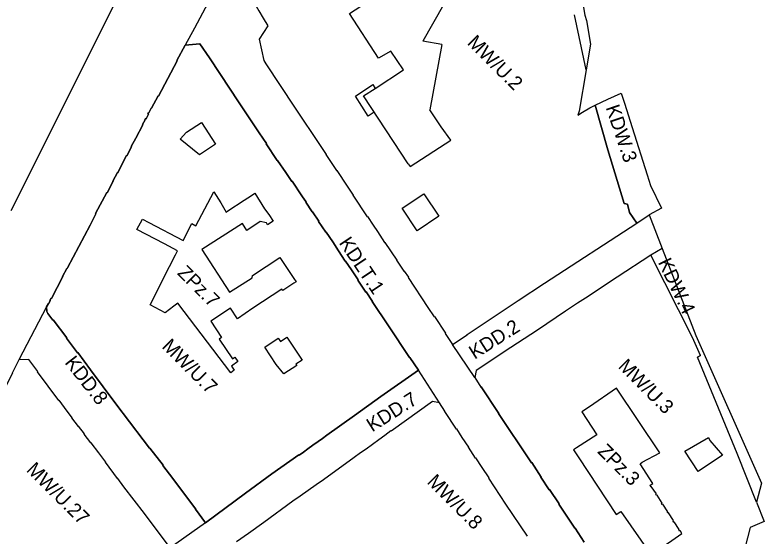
# Model space of a CAD drawing. Extents: x 7423835 to 7425280, y 5546086 to 5547600.
# Drawn here: x 7424423.3 to 7424744.2, y 5546978.5 to 5547201.6 of the extents above; entities that cross this region are included whole.
import ezdxf

# ---------------------------------------------------------------- set-up
doc = ezdxf.new("R2010")
doc.units = 0
for name, color, linetype in [('linie rozgraniczające', 7, 'Continuous'), ('nieprzekraczalne linie zabudowy', 7, 'Continuous'), ('obowiazujace linie zabudowy', 7, 'Continuous'), ('przeznaczenia terenów', 7, 'Continuous')]:
    doc.layers.add(name, color=color, linetype=linetype)

msp = doc.modelspace()

# ---------------------------------------------------------------- linework, layer by layer
at = {"layer": 'linie rozgraniczające'}
for p, q in [((7424421.63, 5547117.9), (7424483.52, 5547241.43)), ((7424668.04, 5547178.09), (7424663, 5547201.56)), ((7424606.16, 5547188.94), (7424598.05, 5547190.36)), ((7424606.16, 5547188.94), (7424601.01, 5547160.97)), ((7424689.69, 5547112.43), (7424694.91, 5547115.93)), ((7424436.81, 5547076.59), (7424424.95, 5547053.95)), ((7424620.22, 5547046.37), (7424610.78, 5547060.48)), ((7424716.92, 5547055.72), (7424715.66, 5547055.1)), ((7424605.11, 5547035.55), (7424596.09, 5547049.53)), ((7424699.58, 5547014.05), (7424681, 5547041.75)), ((7424666.11, 5547031.66), (7424672.53, 5547021.84)), ((7424664.9, 5547011.99), (7424680.83, 5546987.74)), ((7424504.88, 5546984.18), (7424489.79, 5546973.41))]:
    msp.add_line(p, q, dxfattribs=at)
for points in [[(7424515.02, 5547224.22), (7424514.03, 5547222.22), (7424510.28, 5547215.04), (7424500.2, 5547195.98), (7424496.14, 5547188.61)], [(7424515.06, 5547224.71), (7424515.02, 5547224.22), (7424515.98, 5547223.73), (7424524.29, 5547209.32), (7424526.02, 5547206.37), (7424527.74, 5547203.41), (7424529.66, 5547200.13), (7424531.58, 5547196.85), (7424531.58, 5547196.85), (7424527.83, 5547191.15), (7424529.92, 5547182.06), (7424530.79, 5547180.62)], [(7424589.68, 5547178.04), (7424589.68, 5547178.04), (7424584.25, 5547186.11), (7424578.98, 5547183.11), (7424566.55, 5547202.13), (7424571.43, 5547205.35), (7424569.51, 5547209.13), (7424567.47, 5547215.13), (7424566.64, 5547215.54), (7424566.64, 5547215.54)], [(7424665.83, 5547210.62), (7424667.48, 5547201.5), (7424668.06, 5547199.15), (7424669.81, 5547189), (7424668.04, 5547178.09), (7424664.92, 5547160.36), (7424664.39, 5547158.6), (7424666.46, 5547159.91), (7424669.51, 5547161.84), (7424671.82, 5547162.96), (7424677.22, 5547165.58), (7424682.93, 5547168.09), (7424684.38, 5547163.8), (7424687.66, 5547153.42), (7424694.13, 5547133.14), (7424695.52, 5547128.62), (7424700.33, 5547118.84), (7424694.91, 5547115.93), (7424700.59, 5547101.52), (7424714.9, 5547064.29), (7424743.15, 5547001.11), (7424741.02, 5546992.9), (7424744.18, 5546984.74), (7424738.23, 5546982.17), (7424733.48, 5546963.9)], [(7424606.91, 5547205.94), (7424598.05, 5547190.36)], [(7424436.81, 5547076.59), (7424437.63, 5547078.09), (7424437.76, 5547078.01), (7424438.36, 5547079.29), (7424438.28, 5547079.34), (7424438.77, 5547080.27), (7424438.91, 5547080.19), (7424443.83, 5547089.57), (7424443.69, 5547089.64), (7424445.49, 5547093.08), (7424445.67, 5547093.01), (7424445.78, 5547093.3), (7424455.43, 5547111.63), (7424457.98, 5547116.45), (7424457.83, 5547116.52), (7424462.59, 5547125.49), (7424462.73, 5547125.41), (7424465.38, 5547130.41), (7424465.27, 5547130.47), (7424467.15, 5547134.06), (7424467.29, 5547133.99), (7424469.27, 5547137.79), (7424469.15, 5547137.85), (7424471.08, 5547141.39), (7424471.21, 5547141.32), (7424473.24, 5547145.14), (7424473.12, 5547145.23), (7424475.04, 5547148.84), (7424478.06, 5547154.51), (7424477.97, 5547154.61), (7424479.04, 5547156.62), (7424478.96, 5547156.69), (7424479.2, 5547157.17), (7424479.44, 5547157.05), (7424480.45, 5547159.14), (7424480.27, 5547159.22), (7424480.5, 5547159.7), (7424480.62, 5547159.64), (7424481.7, 5547161.67), (7424481.82, 5547161.6), (7424484.63, 5547166.89), (7424484.75, 5547166.83), (7424492.83, 5547181.99), (7424492.67, 5547182.08), (7424496.14, 5547188.61)], [(7424496.14, 5547188.61), (7424502.52, 5547189.17), (7424506.61, 5547183.15), (7424515.48, 5547169.78), (7424518.8, 5547164.78), (7424527.86, 5547151.11), (7424530.97, 5547146.47), (7424530.85, 5547146.39), (7424535.56, 5547139.21), (7424535.71, 5547139.32), (7424539.35, 5547134.14), (7424541.91, 5547130.25), (7424542.04, 5547130.34), (7424546.22, 5547124.15), (7424547.44, 5547122.32), (7424547.98, 5547121.53), (7424547.85, 5547121.44), (7424550.62, 5547117.25), (7424550.76, 5547117.34), (7424553.53, 5547113.23), (7424553.36, 5547113.12), (7424556.44, 5547108.6), (7424556.61, 5547108.63), (7424559.39, 5547104.47), (7424561.94, 5547100.62), (7424561.84, 5547100.52), (7424564.78, 5547096.13), (7424564.91, 5547096.19), (7424567.47, 5547092.38), (7424570.27, 5547088.19), (7424570.15, 5547088.08), (7424573.59, 5547082.95), (7424573.73, 5547083.02), (7424576.44, 5547078.94), (7424576.32, 5547078.85), (7424583.29, 5547068.52), (7424592.35, 5547054.87), (7424592.48, 5547054.93), (7424596.09, 5547049.53)], [(7424530.79, 5547180.62), (7424543.07, 5547162.12), (7424554.29, 5547145.24), (7424556.56, 5547141.85), (7424556.44, 5547141.76), (7424561, 5547134.94), (7424561.13, 5547135.03), (7424565.62, 5547128.32), (7424568.22, 5547124.44), (7424568.09, 5547124.35), (7424574.23, 5547115.19), (7424574.37, 5547115.26), (7424576.8, 5547111.61), (7424578.66, 5547108.86), (7424578.54, 5547108.79), (7424581.65, 5547104.08), (7424581.78, 5547104.16), (7424586.86, 5547096.63), (7424586.73, 5547096.55), (7424589.87, 5547091.87), (7424590.01, 5547091.94), (7424591.82, 5547089.24), (7424591.68, 5547089.15), (7424600.21, 5547076.35), (7424602.91, 5547072.33), (7424603.05, 5547072.41), (7424607.77, 5547065.33), (7424607.63, 5547065.24), (7424610.78, 5547060.48), (7424617.04, 5547064.63), (7424616.97, 5547064.75), (7424630.76, 5547073.82), (7424638.92, 5547079.25), (7424650.2, 5547086.74), (7424689.69, 5547112.43)], [(7424572.65, 5547166.9), (7424577.62, 5547170.15), (7424589.68, 5547178.05)], [(7424591.75, 5547137.85), (7424585.49, 5547147.37), (7424572.65, 5547166.9)], [(7424671.82, 5547162.96), (7424677.23, 5547143.81), (7424684.32, 5547120.8), (7424685.76, 5547120.53), (7424686.5, 5547117.04), (7424689.69, 5547112.43)], [(7424609.97, 5547147.98), (7424605.83, 5547153.73), (7424601.01, 5547160.97)], [(7424591.75, 5547137.85), (7424592.62, 5547136.65), (7424609.97, 5547147.98)], [(7424700.59, 5547101.52), (7424695.7, 5547098.75), (7424681.3, 5547089.27), (7424667.63, 5547080.28), (7424664.28, 5547078.12), (7424659.15, 5547074.74), (7424647.12, 5547066.65), (7424635.68, 5547059.25), (7424620.81, 5547049.34), (7424620.22, 5547046.37), (7424622.92, 5547042.19), (7424623.04, 5547042.28)], [(7424713.55, 5547063.4), (7424695.7, 5547098.75)], [(7424596.09, 5547049.53), (7424580.08, 5547038.16), (7424568.7, 5547030.05), (7424556.86, 5547021.6), (7424554.99, 5547020.25), (7424553.11, 5547018.9), (7424550.92, 5547017.33), (7424548.74, 5547015.76), (7424546.88, 5547014.42), (7424545.02, 5547013.09), (7424544.93, 5547013.21), (7424533.35, 5547005.05), (7424522.08, 5546996.86), (7424504.88, 5546984.18), (7424500.58, 5546989.94), (7424500.71, 5546990.04), (7424489.46, 5547004.95), (7424486.61, 5547008.64), (7424486.73, 5547008.75), (7424481.1, 5547016.14), (7424480.94, 5547016.09), (7424478.24, 5547019.6), (7424466.56, 5547035.13), (7424455.59, 5547049.63), (7424450.15, 5547056.99), (7424450.01, 5547056.88), (7424447.89, 5547059.79), (7424445.32, 5547063.2), (7424445.44, 5547063.29), (7424439.66, 5547070.99), (7424439.52, 5547070.89), (7424437.34, 5547073.69), (7424436.95, 5547074.62), (7424436.81, 5547076.59)], [(7424716.92, 5547055.72), (7424713.55, 5547063.4)], [(7424429.17, 5547053.99), (7424424.95, 5547053.95), (7424422.08, 5547048.27), (7424422.23, 5547048.2), (7424414.59, 5547033.43), (7424414.46, 5547033.49), (7424412.33, 5547029.27), (7424412.45, 5547029.21), (7424410.31, 5547025.17), (7424408.29, 5547021.34), (7424408.44, 5547021.27), (7424403.06, 5547010.72), (7424402.91, 5547010.8), (7424401.09, 5547007.28), (7424398.43, 5547002.08), (7424398.57, 5547002.01), (7424396.07, 5546997.23), (7424395.93, 5546997.28), (7424393.21, 5546992.04), (7424393.33, 5546991.97), (7424388.52, 5546982.69), (7424388.38, 5546982.76), (7424386.34, 5546978.7)], [(7424489.79, 5546973.41), (7424478.72, 5546988.05), (7424469.96, 5546999.56), (7424467.35, 5547003.14), (7424467.22, 5547003.04), (7424462.05, 5547010.07), (7424462.18, 5547010.16), (7424459.24, 5547014.08), (7424455.89, 5547018.43), (7424455.78, 5547018.34), (7424452.96, 5547022.09), (7424453.08, 5547022.18), (7424450.55, 5547025.5), (7424450.44, 5547025.42), (7424447.65, 5547029.07), (7424447.74, 5547029.14), (7424444.52, 5547033.47), (7424442.2, 5547036.58), (7424442.08, 5547036.5), (7424432.98, 5547048.78), (7424433.1, 5547048.87), (7424429.17, 5547053.99)], [(7424741.02, 5546992.9), (7424732.67, 5547013.81), (7424715.66, 5547055.1)], [(7424667.19, 5546975.89), (7424663.24, 5546981.87), (7424663.1, 5546981.79), (7424659.66, 5546986.99), (7424656.23, 5546992.16), (7424656.38, 5546992.25), (7424652.29, 5546998.39), (7424652.15, 5546998.3), (7424648.62, 5547003.67), (7424648.73, 5547003.74), (7424644.7, 5547009.88), (7424644.55, 5547009.79), (7424641.07, 5547014.97), (7424633.29, 5547026.68), (7424630.46, 5547030.9), (7424630.6, 5547030.99), (7424623.04, 5547042.28)], [(7424681, 5547041.75), (7424669.36, 5547033.81), (7424666.11, 5547031.66)], [(7424642.84, 5546978.38), (7424633.62, 5546992.17), (7424626.24, 5547003.28), (7424626.37, 5547003.36), (7424623.41, 5547007.85), (7424620.74, 5547011.88), (7424620.6, 5547011.79), (7424617.52, 5547016.45), (7424617.65, 5547016.55), (7424614.92, 5547020.7), (7424612.51, 5547024.34), (7424612.4, 5547024.26), (7424607.4, 5547031.84), (7424607.51, 5547031.91), (7424605.11, 5547035.55), (7424602.15, 5547036.09), (7424584.43, 5547023.32), (7424584.34, 5547023.44), (7424581.73, 5547021.55), (7424579.21, 5547019.67), (7424576.4, 5547017.65), (7424573.7, 5547015.72), (7424571.38, 5547014.04), (7424568.62, 5547012.03), (7424555.43, 5547002.5), (7424552.28, 5547000.32), (7424545.43, 5546995.48), (7424542.33, 5546993.35), (7424529.87, 5546984.21), (7424523.35, 5546979.58), (7424518.2, 5546975.95)], [(7424672.53, 5547021.84), (7424663.88, 5547016.26), (7424662.6, 5547015.44), (7424664.9, 5547011.99)], [(7424709.02, 5546979.52), (7424708.2, 5546980.77), (7424707.94, 5546980.61), (7424707.64, 5546981.08), (7424707.9, 5546981.24), (7424705.72, 5546984.57), (7424705.5, 5546984.42), (7424705.19, 5546984.89), (7424705.41, 5546985.05), (7424703.25, 5546988.33), (7424703.04, 5546988.2), (7424702.79, 5546988.73), (7424702.94, 5546988.84), (7424700.84, 5546992.11), (7424700.61, 5546991.98), (7424700.3, 5546992.46), (7424700.52, 5546992.6), (7424698.36, 5546995.95), (7424698.15, 5546995.81), (7424697.86, 5546996.4), (7424698.1, 5546996.51), (7424695.9, 5546999.73), (7424695.67, 5546999.6), (7424695.36, 5547000.2), (7424696.57, 5547000.98), (7424691.09, 5547009.45), (7424692.04, 5547010.07), (7424699.58, 5547014.05)], [(7424680.83, 5546987.74), (7424682.81, 5546988.93), (7424695.69, 5546970.54)], [(7424695.69, 5546970.54), (7424703.23, 5546975.57), (7424709.02, 5546979.52)]]:
    msp.add_lwpolyline(points, dxfattribs=at)
msp.add_lwpolyline([(7424536.79, 5547097.73), (7424542.79, 5547088.68), (7424543.7, 5547087.31), (7424543.69, 5547087.3), (7424542.78, 5547086.75), (7424537.97, 5547083.66), (7424537.61, 5547084.22), (7424525.25, 5547075.96), (7424525.25, 5547075.96), (7424525.25, 5547075.96), (7424525.25, 5547075.96), (7424518.61, 5547071.53), (7424515.59, 5547076.05), (7424515.59, 5547076.05), (7424507.19, 5547070.4), (7424507.19, 5547070.4), (7424511.76, 5547063.5), (7424510.82, 5547062.8), (7424516.41, 5547054.36), (7424517.46, 5547055.03), (7424518.72, 5547053.15), (7424516.05, 5547051.26), (7424517.2, 5547049.52), (7424515.77, 5547048.41), (7424493, 5547078.14), (7424491.4, 5547076.94), (7424487.65, 5547073.98), (7424481.23, 5547077.45), (7424489.5, 5547093.86), (7424492.03, 5547098.84), (7424492.96, 5547100.61), (7424487.35, 5547103.53), (7424475.48, 5547109.72), (7424477.85, 5547114.14), (7424480.67, 5547112.67), (7424495.27, 5547105.04), (7424499.07, 5547112.25), (7424499.07, 5547112.25), (7424500.82, 5547111.27), (7424508.44, 5547125.82), (7424508.44, 5547125.82), (7424508.44, 5547125.82), (7424511.54, 5547121.11), (7424513.76, 5547117.2), (7424514.43, 5547117.65), (7424521.44, 5547122.33), (7424524.57, 5547124.28), (7424526.03, 5547125.25), (7424530.24, 5547118.63), (7424532.01, 5547116.08), (7424533.93, 5547113.3), (7424531.5, 5547111.74), (7424530.99, 5547112.59), (7424528.26, 5547113.19), (7424522.55, 5547109.35), (7424520.73, 5547112.26), (7424503.28, 5547101.18), (7424503.28, 5547101.18), (7424503.28, 5547101.18), (7424503.28, 5547101.18), (7424503.28, 5547101.18), (7424503.28, 5547101.18), (7424503.28, 5547101.18), (7424515.16, 5547082.89), (7424524.9, 5547089.08), (7424525.08, 5547090)], close=True, dxfattribs=at)
at = {"layer": 'nieprzekraczalne linie zabudowy'}
for p, q in [((7424668.04, 5547178.09), (7424663, 5547201.56)), ((7424539.73, 5547063.58), (7424546.29, 5547053.7))]:
    msp.add_line(p, q, dxfattribs=at)
for points in [[(7424577.22, 5547159.95), (7424574.54, 5547158.25), (7424569.1, 5547166.77), (7424576.63, 5547171.73), (7424577.62, 5547170.15)], [(7424689.69, 5547112.43), (7424686.5, 5547117.04), (7424685.76, 5547120.53), (7424684.32, 5547120.8), (7424677.23, 5547143.81), (7424671.82, 5547162.96)], [(7424741.02, 5546992.9), (7424732.67, 5547013.81), (7424715.66, 5547055.1), (7424716.92, 5547055.7), (7424713.55, 5547063.4), (7424695.7, 5547098.75)], [(7424538.53, 5547047.86), (7424535.24, 5547051.97), (7424530.27, 5547059.37)]]:
    msp.add_lwpolyline(points, dxfattribs=at)
for points in [[(7424503.21, 5547155.5), (7424509.18, 5547146.2), (7424502.32, 5547141.65), (7424494.12, 5547148.43), (7424496.83, 5547151.44)], [(7424598.46, 5547124.95), (7424604.84, 5547115.43), (7424595.65, 5547109.13), (7424589.18, 5547118.81)], [(7424720.96, 5547019.38), (7424726.41, 5547013.07), (7424715.97, 5547006.16), (7424710.22, 5547014.85), (7424720.39, 5547020.66)]]:
    msp.add_lwpolyline(points, close=True, dxfattribs=at)
at = {"layer": 'obowiazujace linie zabudowy'}
for points in [[(7424515.06, 5547224.71), (7424515.02, 5547224.22), (7424515.98, 5547223.73), (7424524.29, 5547209.32), (7424526.02, 5547206.37), (7424527.74, 5547203.41), (7424529.66, 5547200.13), (7424531.58, 5547196.85), (7424531.58, 5547196.85), (7424527.83, 5547191.15), (7424529.92, 5547182.06), (7424530.79, 5547180.62)], [(7424496.14, 5547188.61), (7424492.67, 5547182.08), (7424492.83, 5547181.99), (7424484.75, 5547166.83), (7424484.63, 5547166.89), (7424481.82, 5547161.6), (7424481.7, 5547161.67), (7424480.62, 5547159.64), (7424480.5, 5547159.7), (7424480.27, 5547159.22), (7424480.45, 5547159.14), (7424479.44, 5547157.05), (7424479.2, 5547157.17), (7424478.96, 5547156.69), (7424479.04, 5547156.62), (7424477.97, 5547154.61), (7424478.06, 5547154.51), (7424475.04, 5547148.84), (7424473.12, 5547145.23), (7424473.24, 5547145.14), (7424471.21, 5547141.32), (7424471.08, 5547141.39), (7424469.15, 5547137.85), (7424469.27, 5547137.79), (7424467.29, 5547133.99), (7424467.15, 5547134.06), (7424465.27, 5547130.47), (7424465.38, 5547130.41), (7424462.73, 5547125.41), (7424462.59, 5547125.49), (7424457.83, 5547116.52), (7424457.98, 5547116.45), (7424455.43, 5547111.63), (7424445.78, 5547093.3), (7424445.67, 5547093.01), (7424445.49, 5547093.08), (7424443.69, 5547089.64), (7424443.83, 5547089.57), (7424438.91, 5547080.19), (7424438.77, 5547080.27), (7424438.28, 5547079.34), (7424438.36, 5547079.29), (7424437.76, 5547078.01), (7424437.63, 5547078.09), (7424436.81, 5547076.59)], [(7424596.09, 5547049.53), (7424592.48, 5547054.93), (7424592.35, 5547054.87), (7424583.29, 5547068.52), (7424576.32, 5547078.85), (7424576.44, 5547078.94), (7424573.73, 5547083.02), (7424573.59, 5547082.95), (7424570.15, 5547088.08), (7424570.27, 5547088.19), (7424567.47, 5547092.38), (7424564.91, 5547096.19), (7424564.78, 5547096.13), (7424561.84, 5547100.52), (7424561.94, 5547100.62), (7424559.39, 5547104.47), (7424556.61, 5547108.63), (7424556.44, 5547108.6), (7424553.36, 5547113.12), (7424553.53, 5547113.23), (7424550.76, 5547117.34), (7424550.62, 5547117.25), (7424547.85, 5547121.44), (7424547.98, 5547121.53), (7424547.44, 5547122.32), (7424546.22, 5547124.15), (7424542.04, 5547130.34), (7424541.91, 5547130.25), (7424539.35, 5547134.14), (7424535.71, 5547139.32), (7424535.56, 5547139.21), (7424530.85, 5547146.39), (7424530.97, 5547146.47), (7424527.86, 5547151.11), (7424518.8, 5547164.78), (7424515.48, 5547169.78), (7424506.61, 5547183.15), (7424502.52, 5547189.17), (7424496.14, 5547188.61)], [(7424530.79, 5547180.62), (7424543.07, 5547162.12), (7424554.29, 5547145.24), (7424556.56, 5547141.85), (7424556.44, 5547141.76), (7424561, 5547134.94), (7424561.13, 5547135.03), (7424565.62, 5547128.32), (7424568.22, 5547124.44), (7424568.09, 5547124.35), (7424574.23, 5547115.19), (7424574.37, 5547115.26), (7424576.8, 5547111.61), (7424578.66, 5547108.86), (7424578.54, 5547108.79), (7424581.65, 5547104.08), (7424581.78, 5547104.16), (7424586.86, 5547096.63), (7424586.73, 5547096.55), (7424589.87, 5547091.87), (7424590.01, 5547091.94), (7424591.82, 5547089.24), (7424591.68, 5547089.15), (7424600.21, 5547076.35), (7424602.91, 5547072.33), (7424603.05, 5547072.41), (7424607.77, 5547065.33), (7424607.63, 5547065.24), (7424610.78, 5547060.48), (7424617.04, 5547064.63), (7424616.97, 5547064.75), (7424630.76, 5547073.82), (7424638.92, 5547079.25), (7424650.2, 5547086.74), (7424689.69, 5547112.43)], [(7424700.59, 5547101.52), (7424695.7, 5547098.75), (7424681.3, 5547089.27), (7424667.63, 5547080.28), (7424664.28, 5547078.12), (7424659.15, 5547074.74), (7424647.12, 5547066.65), (7424635.68, 5547059.25), (7424620.81, 5547049.34), (7424620.22, 5547046.37), (7424622.92, 5547042.19), (7424623.04, 5547042.28)], [(7424436.81, 5547076.59), (7424436.95, 5547074.62), (7424437.34, 5547073.69), (7424439.52, 5547070.89), (7424439.66, 5547070.99), (7424445.44, 5547063.29), (7424445.32, 5547063.2), (7424447.89, 5547059.79), (7424450.01, 5547056.88), (7424450.15, 5547056.99), (7424455.59, 5547049.63), (7424466.56, 5547035.13), (7424478.24, 5547019.6), (7424480.94, 5547016.09), (7424481.1, 5547016.14), (7424486.73, 5547008.75), (7424486.61, 5547008.64), (7424489.46, 5547004.95), (7424500.71, 5546990.04), (7424500.58, 5546989.94), (7424504.88, 5546984.18), (7424522.08, 5546996.86), (7424533.35, 5547005.05), (7424544.93, 5547013.21), (7424545.02, 5547013.09), (7424546.88, 5547014.42), (7424548.74, 5547015.76), (7424550.92, 5547017.33), (7424553.11, 5547018.9), (7424554.99, 5547020.25), (7424556.86, 5547021.6), (7424568.7, 5547030.05), (7424580.08, 5547038.16), (7424596.09, 5547049.53)], [(7424530.27, 5547059.37), (7424536.02, 5547063.18), (7424536.97, 5547061.76), (7424539.73, 5547063.58)], [(7424429.17, 5547053.99), (7424424.95, 5547053.95), (7424422.08, 5547048.27), (7424422.23, 5547048.2), (7424414.59, 5547033.43), (7424414.46, 5547033.49), (7424412.33, 5547029.27), (7424412.45, 5547029.21), (7424410.31, 5547025.17), (7424408.29, 5547021.34), (7424408.44, 5547021.27), (7424403.06, 5547010.72), (7424402.91, 5547010.8), (7424401.09, 5547007.28), (7424398.43, 5547002.08), (7424398.57, 5547002.01), (7424396.07, 5546997.23), (7424395.93, 5546997.28), (7424393.21, 5546992.04), (7424393.33, 5546991.97), (7424388.52, 5546982.69), (7424388.38, 5546982.76), (7424386.34, 5546978.7)], [(7424489.79, 5546973.41), (7424478.72, 5546988.05), (7424469.96, 5546999.56), (7424467.35, 5547003.14), (7424467.22, 5547003.04), (7424462.05, 5547010.07), (7424462.18, 5547010.16), (7424459.24, 5547014.08), (7424455.89, 5547018.43), (7424455.78, 5547018.34), (7424452.96, 5547022.09), (7424453.08, 5547022.18), (7424450.55, 5547025.5), (7424450.44, 5547025.42), (7424447.65, 5547029.07), (7424447.74, 5547029.14), (7424444.52, 5547033.47), (7424442.2, 5547036.58), (7424442.08, 5547036.5), (7424432.98, 5547048.78), (7424433.1, 5547048.87), (7424429.17, 5547053.99)], [(7424546.29, 5547053.7), (7424543.67, 5547052.03), (7424544, 5547051.51), (7424538.53, 5547047.86)], [(7424623.04, 5547042.28), (7424630.6, 5547030.99), (7424630.46, 5547030.9), (7424633.29, 5547026.68), (7424641.07, 5547014.97), (7424644.55, 5547009.79), (7424644.7, 5547009.88), (7424648.73, 5547003.74), (7424648.62, 5547003.67), (7424652.15, 5546998.3), (7424652.29, 5546998.39), (7424656.38, 5546992.25), (7424656.23, 5546992.16), (7424659.66, 5546986.99), (7424663.1, 5546981.79), (7424663.24, 5546981.87), (7424667.19, 5546975.89)], [(7424642.84, 5546978.38), (7424633.62, 5546992.17), (7424626.24, 5547003.28), (7424626.37, 5547003.36), (7424623.41, 5547007.85), (7424620.74, 5547011.88), (7424620.6, 5547011.79), (7424617.52, 5547016.45), (7424617.65, 5547016.55), (7424614.92, 5547020.7), (7424612.51, 5547024.34), (7424612.4, 5547024.26), (7424607.4, 5547031.84), (7424607.51, 5547031.91), (7424605.11, 5547035.55), (7424602.15, 5547036.09), (7424584.43, 5547023.32), (7424584.34, 5547023.44), (7424581.73, 5547021.55), (7424579.21, 5547019.67), (7424576.4, 5547017.65), (7424573.7, 5547015.72), (7424571.38, 5547014.04), (7424568.62, 5547012.03), (7424555.43, 5547002.5), (7424552.28, 5547000.32), (7424545.43, 5546995.48), (7424542.33, 5546993.35), (7424529.87, 5546984.21), (7424523.35, 5546979.58), (7424518.2, 5546975.95)]]:
    msp.add_lwpolyline(points, dxfattribs=at)

# ---------------------------------------------------------------- texts
at = {"layer": 'przeznaczenia terenów'}
for s, rotation, p in [('MW/U.2', 314.9764, (7424616.7, 5547189.34)), ('KDW.3', 288.6259, (7424676.27, 5547161.97)), ('KDLT.1', 303.6529, (7424561.88, 5547104.02)), ('KDW.4', 295.6858, (7424698.59, 5547095.69)), ('ZPz.7', 314.9764, (7424492.53, 5547090.74)), ('KDD.2', 32.3444, (7424620.19, 5547053.92)), ('MW/U.7', 314.9764, (7424485.9, 5547059.33)), ('KDD.8', 308.0245, (7424444.32, 5547052.66)), ('MW/U.3', 314.9764, (7424681.33, 5547050.76)), ('KDD.7', 32.3444, (7424576.32, 5547022.8)), ('ZPz.3', 314.9764, (7424672.55, 5547014.34)), ('MW/U.27', 314.9764, (7424427.84, 5547006.45)), ('MW/U.8', 314.9764, (7424599.48, 5547001.3))]:
    msp.add_text(s, height=6, rotation=rotation, dxfattribs=at).set_placement(p)

doc.saveas('drawing.dxf')
